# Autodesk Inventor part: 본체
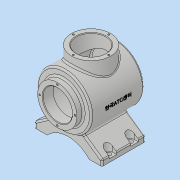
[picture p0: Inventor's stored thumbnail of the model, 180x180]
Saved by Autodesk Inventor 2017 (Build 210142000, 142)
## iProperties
Part Number: 본체
Material: 일반
Document SubType Name: Modeling
Designer: MRC
Density: 1 g/cm^3
Appearance: 기본값
Author: MRC
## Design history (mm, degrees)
sketch "스케치1"
  geometry: L1 (0, 62)-(0, -58); L2 (27, 62)-(27, 43); L3 (27, 43)-(43, 43); L4 (43, 43)-(43, -41.887); L5 (27, 62)-(36, 62); L6 (36, 62)-(36, 50); L7 (36, 50)-(50, 50); L8 (50, 50)-(50, -46.336); L9 (0, -58)-(0, -51); A1 r 106 centre (0, 55) between (0, -51) and (43, -41.887); A2 r 113 centre (0, 55) between (0, -58) and (50, -46.336); 2 further points
  constraints: 18 end point, 4 point on circle, 3 vertical, 2 centre point, 2 horizontal, 2 perpendicular, 2 point on line, 1 collinear, 1 concentric, 1 horizontal alignment, 1 midpoint, 1 parallel, 1 vertical alignment
  dimensions: "d0" = 62 distance of point (0, 0) L1.start; "d1" = 120 distance of L1.start L1.end; "d2" = 54 diameter of L2 L1; "d3" = 72 diameter of L6 L1; "d4" = 86 diameter of L4 L1; "d5" = 100 diameter of L8 L1; "d6" = 108 distance from line of L7 L1.end; "d7" = 113 radius of A2; "d8" = 7 radial gap between concentric circles of A1 A2; "d9" = 19 distance of L2.start L2.end
revolve "회전1" sketch "스케치1" stored, may be unused: angle "d10" = 90 deg
node "작업 평면1"
sketch "스케치2"
  geometry: C1 r 36 at (0, 0); 1 further point
  constraints: 1 centre point, 1 coincident
  dimensions: "d12" = 72 diameter of C1
extrude "돌출1" join sketch "스케치2" stored distance "d13" = 10; taper "d14" = 0 deg
sketch "스케치3"
  geometry: C1 r 27 at (0, 0); 1 further point
  constraints: 1 centre point, 1 coincident
  dimensions: "d15" = 54 diameter of C1
extrude "돌출2" cut sketch "스케치3" stored distance "d16" = 10; taper "d17" = 0 deg
node "작업 평면2"
sketch "스케치4"
  geometry: L1 (-26.694, -42.278)-(-62, -67); L2 (-62, -67)-(-62, -77); L3 (-62, -77)-(-38.5, -77); L4 (26.694, -42.278)-(62, -67); L5 (62, -67)-(62, -77); L6 (62, -77)-(38.5, -77); A1 r 50 centre (0, 0) between (-26.694, -42.278) and (26.694, -42.278) reference; A2 r 52.096 centre (0, -112.096) between (38.5, -77) and (-38.5, -77); 1 further point
  constraints: 12 end point, 4 point on circle, 2 collinear, 2 perpendicular, 2 vertical, 1 centre point, 1 vertical alignment
  dimensions: "d19" = 77 distance from line of L6 point (0, 0); "d20" = 77 distance of L3.end L6.end; "d21" = 10 distance of L4.end L5.end; "d22" = 55 deg angle of L5 L4; "d23" = 17 distance edge to line of A2 L6; "d24" = 55 deg angle of L2 L1; "d25" = 10 distance of L1.end L2.end; "d26" = 124 distance between parallel lines of L5 L2
extrude "돌출3" join sketch "스케치4" stored distance "d27" = 80; taper "d28" = 0 deg
sketch "스케치5"
  geometry: 2 further points
  constraints: 1 vertical alignment
  dimensions: "d29" = 32.5 distance of point (0, 32.5) point (0, 0)
hole "구멍1" sketch "스케치5" at (0, 32.5) diameter "d30" = 3.242; stored, may be unused: countersink angle "d34" = 90 deg, drill point angle "d36" = 118 deg; dims "d31" = 8, "d32" = 4, "d33" = 2, "d35" = 10
sketch "스케치6"
  geometry: 2 further points
  constraints: 1 vertical alignment
  dimensions: "d40" = 32.5 distance of point (0, 32.5) point (0, 0)
hole "구멍2" sketch "스케치6" at (0, 32.5) diameter "d41" = 3.242; stored, may be unused: countersink angle "d45" = 90 deg, drill point angle "d47" = 118 deg; dims "d42" = 8, "d43" = 4, "d44" = 2, "d46" = 10
sketch "스케치7"
  geometry: L1 (0, 0)-(23.5, 0) reference; C1 r 4.5 at (8, -20); 1 further point
  constraints: 1 centre point
  dimensions: "d51" = 9 diameter of C1; "d52" = 54 horizontal distance of point (62, -42) C1.centre; "d53" = 20 distance from line of C1.centre L1
extrude "돌출4" cut sketch "스케치7" distance "d54" = 6; taper "d55" = 0 deg
sketch "스케치8"
  geometry: L1 (-8, 7)-(0, 7); L2 (-8, -7)-(0, -7); L3 (-8, -60)-(-8, 20) reference; C1 r 4.5 at (0, 0) reference; A1 r 7 centre (0, 0) between (0, -7) and (0, 7); 1 further point
  constraints: 4 end point, 2 horizontal, 2 point on circle, 2 point on line, 2 tangent, 1 centre point, 1 concentric
  dimensions: "d56" = 14 diameter of A1
extrude "돌출5" cut sketch "스케치8" stored distance "d57" = 6; taper "d58" = 0 deg
node "작업 평면3"
chamfer "모따기1" distance "d59" = 1; stored, may be unused: second distance "d60" = 2, angle "d61" = 45 deg
fillet "모깎기1" dims "d62" = 3
fillet "모깎기2" dims "d63" = 3
fillet "모깎기3" dims "d64" = 3
fillet "모깎기4" dims "d65" = 3
node "작업 평면4"
sketch "스케치9"
  geometry: 2 further points
  constraints: 1 coincident, 1 other
feature "엠보싱1" sketch "스케치9" dims "d67" = 0.5, "d68" = 0
node "솔리드1"
pattern_circular "원형 패턴1" dims angle "d38" = 360 deg
pattern_circular "원형 패턴2" dims angle "d49" = 360 deg
mirror "미러1"
mirror "미러2"
other parameters: "d11" = 65
